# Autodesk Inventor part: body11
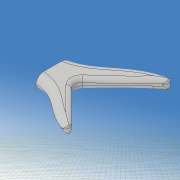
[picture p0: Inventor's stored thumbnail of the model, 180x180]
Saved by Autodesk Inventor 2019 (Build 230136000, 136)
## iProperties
Created: 2020-12
Part Number: body11
Material: 一般
Document SubType Name: Modeling
Designer: kikut
Density: 1 g/cm^3
Appearance: 既定
Mass: 87.6477 g
Surface Area: 156.124 cm^2
Volume: 87.6477 cm^3
Author: kikut
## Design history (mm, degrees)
sketch "スケッチ1"
  geometry: L1 (-100, -20)-(100, -20); L2 (100, -20)-(100, 20); L3 (100, 20)-(-100, 20); L4 (-100, 20)-(-100, -20); L5 (-100, -20)-(100, 20); L6 (100, -20)-(-100, 20); 1 further point
  constraints: 12 end point, 2 midpoint, 2 parallel, 1 horizontal, 1 perpendicular
  dimensions: "d0" = 40 distance of L3.end L1.start; "d1" = 200 distance of L2.end L3.end
extrude "押し出し1" new body sketch "スケッチ1" stored distance "d2" = 60; taper "d3" = 0 deg
sketch "スケッチ2"
  geometry: L1 (0, -60)-(0, 0) reference; L2 (200, -60)-(200, 0) reference; L3 (0, 0)-(200, 0) reference; L4 (200, -60)-(0, -60) reference; L5 (0, -26)-(0, -32); L6 (194, -10)-(194, -13); L7 (194, -13)-(174, -33); L8 (174, -33)-(200, -58); L9 (-20, 20)-(220, 20); L10 (220, 20)-(220, -100); L11 (220, -100)-(-20, -100); L12 (-20, -100)-(-20, 20); 12 further points
  constraints: 16 end point, 4 point on line, 2 parallel, 2 vertical, 1 horizontal, 1 perpendicular, 14 other
  dimensions: "d4" = 32 distance from line of point (32, -12) L1; "d5" = 50 horizontal distance of point (32, -12) point (82, -11); "d6" = 50 horizontal distance of point (132, -17) point (82, -11); "d7" = 12 distance from line of point (32, -12) L3; "d8" = 11 distance from line of point (82, -11) L3; "d10" = 17 distance from line of point (132, -17) L3; "d11" = 26 distance from line of L5.start L3; "d12" = 0 distance from line of point (200, -60) L4; "d13" = 28 distance from line of L5.end L4; "d14" = 12 distance from line of point (28, -48) L4; "d15" = 10 distance from line of point (80, -50) L4; "d16" = 16 distance from line of point (130, -44) L4; "d17" = 28 distance from line of point (28, -48) L1; "d19" = 50 horizontal distance of point (130, -44) point (80, -50); "d20" = 80 distance from line of point (80, -50) L1; "d21" = 6 distance from line of L6.start L2; "d22" = 36 distance from line of point (164, -24) L2; "d23" = 24 distance from line of point (176, -20) L2; "d24" = 10 distance from line of L6.start L3; "d25" = 20 distance from line of point (176, -20) L3; "d26" = 24 distance from line of point (164, -24) L3; "d27" = 40 distance from line of point (160, -40) L2; "d28" = 25 distance from line of point (175, -47.5) L2; "d29" = 12.5 distance from line of point (175, -47.5) L4; "d30" = 20 distance from line of L4 point (160, -40); "d31" = 3 distance of L6.start L6.end; "d32" = 33 distance from line of L7.end L3; "d33" = 26 distance from line of L7.end L2; "d34" = 2 distance of L8.end L2.start; "d35" = 120 distance of L11.end L9.start; "d36" = 240 distance of L10.end L11.end; "d37" = 20 distance between parallel lines of L1 L12; "d38" = 20 distance between parallel lines of L3 L9
extrude "押し出し2" cut sketch "スケッチ2" extent not by distance; stored distance "d39" = 0.02; taper "d40" = 0 deg
sketch "スケッチ8"
  geometry: L1 (-100, -20)-(-100, 20) reference; L2 (100, 20)-(100, -20) reference; L3 (-142.805, 0)-(142.831, 0) reference; L4 (110, 30)-(-110, 30); L5 (-110, 30)-(-110, -30); L6 (-110, -30)-(110, -30); L7 (110, -30)-(110, 30); L8 (110, 30)-(-110, -30); L9 (-110, 30)-(110, -30); L10 (-100, -2)-(-100, 2); L11 (100, -3)-(100, 3); 7 further points
  constraints: 16 end point, 4 point on line, 2 midpoint, 2 parallel, 2 perpendicular, 1 collinear, 1 horizontal, 10 other
  dimensions: "d93" = 2 vertical distance of point (0, 0) L10.end; "d94" = 2 vertical distance of L10.start point (0, 0); "d95" = 35 distance from line of point (-65, -10) L1; "d96" = 0 horizontal distance of point (-65, 10) point (-65, -10); "d97" = 10 vertical distance of point (0, 0) point (-65, -10); "d98" = 10 vertical distance of point (-65, 10) point (0, 0); "d99" = 100 distance from line of point (0, -10) L1; "d100" = 0 horizontal distance of point (0, 10) point (0, -10); "d101" = 10 distance of point (0, -10) point (0, 0); "d102" = 10 distance of point (0, 0) point (0, 10); "d103" = 160 distance from line of point (60, -4) L1; "d104" = 0 horizontal distance of point (60, 4) point (60, -4); "d105" = 4 distance from line of L3 point (60, -4); "d106" = 4 distance from line of L3 point (60, 4); "d107" = 3 distance from line of L11.start L3; "d108" = 3 distance from line of L11.end L3; "d109" = 220 distance of L5.end L6.end; "d110" = 60 distance of L4.end L5.end
extrude "押し出し6" cut sketch "スケッチ8" extent not by distance; stored distance "d111" = 10; taper "d112" = 0 deg
sketch "スケッチ9" dims "d113" = 20, "d114" = 12
  geometry: L1 (-29, -18)-(21, -18); L2 (21, -18)-(21, 22); L3 (21, 22)-(-29, 22); L4 (-29, 22)-(-29, -18); L5 (-29, -18)-(21, 22); L6 (21, -18)-(-29, 22); 2 further points; 1 other entity
  constraints: 12 end point, 2 midpoint, 2 parallel, 1 coincident, 1 horizontal, 1 perpendicular, 2 other
  dimensions: "d115" = 50 distance of L2.end L3.end; "d116" = 40 distance of L1.end L2.end
extrude "押し出し7" cut sketch "スケッチ9" distance "d117" = 150; taper "d118" = 0 deg
fillet "フィレット4" dims "d119" = 4
fillet "フィレット5" dims "d120" = 4
fillet "フィレット6" dims "d121" = 2
node "作業平面2"
sketch "スケッチ10"
  geometry: L1 (0, -41.439)-(0, 38.458) reference; L2 (141.833, 0)-(-140.631, 0) reference; L3 (82.55, 12.983)-(81.45, -4.983); A1 r 9 centre (82, 4) between (82.55, 12.983) and (81.45, -4.983); 1 further point
  constraints: 2 end point, 2 point on circle, 1 centre point
  dimensions: "d123" = 82 distance from line of L1 A1.centre; "d124" = 4 distance from line of L2 A1.centre; "d125" = 9 radius of A1; "d126" = 180 deg dimension on A1.centre L3.end L3.start; "d127" = 90 deg dimension on L3.end point (0, 0) A1.centre
revolve "回転1" sketch "スケッチ10" stored, may be unused: angle "d128" = 90 deg
mirror "ミラー1"
sketch "スケッチ11"
  geometry: L1 (-65, 30)-(-105, 30); L2 (-105, 30)-(-105, -30); L3 (-105, -30)-(-65, -30); L4 (-65, -30)-(-65, 30); L5 (0, -40.648)-(0, 34.486) reference; L6 (140.69, 0)-(-139.196, 0) reference; L7 (120, 53.792)-(-120, 53.792); L8 (-120, 53.792)-(-120, -46.208); L9 (-120, -46.208)-(120, -46.208); L10 (120, -46.208)-(120, 53.792); 1 further point
  constraints: 16 end point, 4 parallel, 2 horizontal, 2 perpendicular, 2 other
  dimensions: "d130" = 40 distance of L1.start L1.end; "d131" = 60 distance of L3.end L1.start; "d132" = 100 distance of L9.end L7.start; "d133" = 240 distance of L7.start L7.end; "d138" = 65 distance between parallel lines of L4 L5
extrude "押し出し8" cut sketch "スケッチ11" stored distance "d134" = 40; taper "d135" = 0 deg
node "ソリッド1"
other parameters: "d122" = -1
